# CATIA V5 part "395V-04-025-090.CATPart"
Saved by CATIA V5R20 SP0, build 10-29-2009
Part number: 395V-04-025-090
Source: Unknown
Property "A": "0.000"
Property "ARTICLENO": "395V-04-025-090"
Property "BOMINFO": "395V-04-025-090"
Property "CODE": "395V-04-025-090"
Property "D": "20.000"
Property "D1": "11.500"
Property "D2": "17.500"
Property "D3": "30.000"
Property "FORM": "A"
Property "L": "90.000"
Property "L1": "10.000"
Property "L2": "37.000"
Property "L3": "25.000"
Property "L4": "8.000"
Property "LINA": "395V-04-025-090"
Property "MAXLOAD": "630 Kg"
Property "MDW": "1260 Kg"
Property "NB": "395V-04-025-090"
Property "NBSYN": "$CODE."
Property "NN": "395V"
Property "NT": "VDI 3366 Lifting Brackets"
Property "SUPPLIER": "CF"
Property "T": "11.000"
Property "W": "25.000"
Bounding box of the stored display mesh (mm): x -12.5 to 12.5, y 0 to 90, z -12.5 to 12.5
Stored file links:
  C:\Users\Utente\Desktop\3D files 395V\395V-04-025-090.CATPart
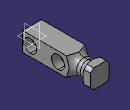
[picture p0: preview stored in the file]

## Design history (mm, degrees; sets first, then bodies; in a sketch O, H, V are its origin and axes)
Body1 "Geometry.1" (main body)
  Solid1 "395V-04-025-090.catpart": solid without history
